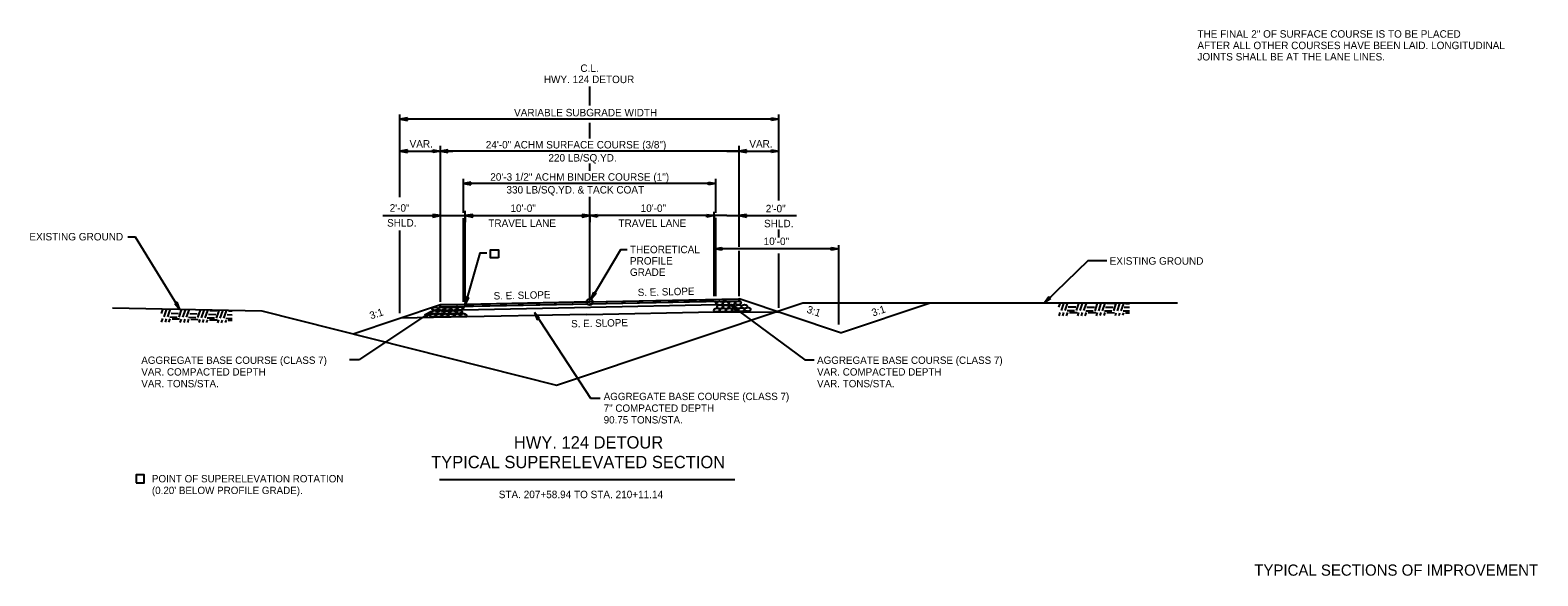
# Model space of a CAD drawing. Extents: x 1824008 to 1828864, y 689441 to 689870.
# Drawn here: x 1828742.7 to 1828863.8, y 689611.6 to 689655.5 of the extents above; entities that cross this region are included whole.
import ezdxf

# ---------------------------------------------------------------- set-up
doc = ezdxf.new("R2010")
doc.units = 0
for name, color, linetype in [('1', 7, 'Continuous'), ('19', 7, 'Continuous'), ('42', 7, 'Continuous'), ('Level 1', 7, 'Continuous'), ('Level 9', 7, 'Continuous'), ('R_Draft', 7, 'Continuous'), ('R_Horz Alg', 7, 'Continuous')]:
    doc.layers.add(name, color=color, linetype=linetype)

# ---------------------------------------------------------------- blocks, each defined once
blk = doc.blocks.new('ROCKS')
at = {"layer": '1'}
blk.add_spline([(0.013, 0.06), (0.053, 0.053), (0.107, 0.033), (0.133, 0.013), (0.133, -0.007), (0.12, -0.033), (0.107, -0.04), (0.073, -0.053), (0.033, -0.067), (0.013, -0.067), (-0.02, -0.06), (-0.06, -0.053), (-0.087, -0.047), (-0.113, -0.02), (-0.113, -0.007), (-0.107, 0.02), (-0.087, 0.033), (-0.067, 0.047), (-0.033, 0.053), (-0.02, 0.06), (0.013, 0.06)], degree=3, dxfattribs=at)

msp = doc.modelspace()

# ---------------------------------------------------------------- linework, layer by layer
at = {"layer": '1'}
for p, q in [((1828772.95, 689648.43), (1828772.35, 689648.33)), ((1828772.35, 689648.33), (1828772.95, 689648.22)), ((1828772.95, 689648.38), (1828772.51, 689648.34)), ((1828772.51, 689648.31), (1828772.95, 689648.27)), ((1828772.95, 689648.22), (1828772.95, 689648.43)), ((1828802.2, 689648.22), (1828802.2, 689648.43)), ((1828802.2, 689648.43), (1828802.8, 689648.33)), ((1828802.2, 689648.38), (1828802.64, 689648.34)), ((1828802.8, 689648.33), (1828802.2, 689648.22)), ((1828802.64, 689648.31), (1828802.2, 689648.27)), ((1828772.95, 689645.85), (1828772.35, 689645.74)), ((1828772.35, 689645.74), (1828772.95, 689645.64)), ((1828772.95, 689645.79), (1828772.51, 689645.76)), ((1828772.51, 689645.73), (1828772.95, 689645.69)), ((1828772.95, 689645.64), (1828772.95, 689645.85)), ((1828775, 689645.64), (1828775, 689645.85)), ((1828775, 689645.85), (1828775.6, 689645.74)), ((1828775, 689645.79), (1828775.44, 689645.76)), ((1828775.6, 689645.74), (1828775, 689645.64)), ((1828775.44, 689645.73), (1828775, 689645.69)), ((1828776.2, 689645.85), (1828775.6, 689645.74)), ((1828775.6, 689645.74), (1828776.2, 689645.64)), ((1828776.2, 689645.79), (1828775.76, 689645.76)), ((1828775.76, 689645.73), (1828776.2, 689645.69)), ((1828776.2, 689645.64), (1828776.2, 689645.85)), ((1828800.2, 689645.85), (1828799.6, 689645.74)), ((1828799.6, 689645.74), (1828800.2, 689645.64)), ((1828800.2, 689645.79), (1828799.76, 689645.76)), ((1828799.76, 689645.73), (1828800.2, 689645.69)), ((1828800.2, 689645.64), (1828800.2, 689645.85)), ((1828802.2, 689645.64), (1828802.2, 689645.85)), ((1828802.2, 689645.85), (1828802.8, 689645.74)), ((1828802.2, 689645.79), (1828802.64, 689645.76)), ((1828802.8, 689645.74), (1828802.2, 689645.64)), ((1828802.64, 689645.73), (1828802.2, 689645.69)), ((1828778.05, 689643.26), (1828777.45, 689643.15)), ((1828777.45, 689643.15), (1828778.05, 689643.05)), ((1828778.05, 689643.2), (1828777.61, 689643.17)), ((1828777.61, 689643.14), (1828778.05, 689643.1)), ((1828778.05, 689643.05), (1828778.05, 689643.26)), ((1828797.14, 689643.05), (1828797.14, 689643.26)), ((1828797.14, 689643.26), (1828797.74, 689643.15)), ((1828797.14, 689643.2), (1828797.58, 689643.17)), ((1828797.74, 689643.15), (1828797.14, 689643.05)), ((1828797.58, 689643.14), (1828797.14, 689643.1)), ((1828775, 689640.67), (1828775, 689640.46)), ((1828775.6, 689640.57), (1828775, 689640.67)), ((1828777.6, 689633.64), (1828777.6, 689640.97)), ((1828778.2, 689640.67), (1828777.6, 689640.57)), ((1828778.2, 689640.46), (1828778.2, 689640.67)), ((1828787, 689640.67), (1828787, 689640.46)), ((1828787.6, 689640.57), (1828787, 689640.67)), ((1828787, 689640.67), (1828787, 689640.46)), ((1828787.6, 689640.57), (1828787, 689640.67)), ((1828787.6, 689640.57), (1828788.2, 689640.67)), ((1828787.6, 689640.57), (1828788.2, 689640.67)), ((1828788.2, 689640.67), (1828788.2, 689640.46)), ((1828788.2, 689640.67), (1828788.2, 689640.46)), ((1828797, 689640.46), (1828797, 689640.67)), ((1828797, 689640.67), (1828797.6, 689640.57)), ((1828797.6, 689634.09), (1828797.6, 689640.87)), ((1828799.6, 689638.07), (1828799.6, 689640.87)), ((1828800.2, 689640.67), (1828799.6, 689640.57)), ((1828800.2, 689640.46), (1828800.2, 689640.67)), ((1828775.44, 689640.58), (1828775, 689640.62)), ((1828775, 689640.46), (1828775.6, 689640.57)), ((1828775, 689640.51), (1828775.44, 689640.55)), ((1828776.6, 689640.57), (1828787.6, 689640.57)), ((1828777.6, 689640.57), (1828787.6, 689640.57)), ((1828777.6, 689640.57), (1828778.2, 689640.46)), ((1828777.6, 689640.57), (1828777.6, 689640.05)), ((1828778.2, 689640.62), (1828777.76, 689640.58)), ((1828777.76, 689640.55), (1828778.2, 689640.51)), ((1828787.44, 689640.58), (1828787, 689640.62)), ((1828787.44, 689640.58), (1828787, 689640.62)), ((1828787, 689640.46), (1828787.6, 689640.57)), ((1828787, 689640.46), (1828787.6, 689640.57)), ((1828787, 689640.51), (1828787.44, 689640.55)), ((1828787, 689640.51), (1828787.44, 689640.55)), ((1828797.6, 689640.57), (1828787.6, 689640.57)), ((1828788.2, 689640.46), (1828787.6, 689640.57)), ((1828797.6, 689640.57), (1828787.6, 689640.57)), ((1828788.2, 689640.46), (1828787.6, 689640.57)), ((1828798.6, 689640.57), (1828787.6, 689640.57)), ((1828787.6, 689640.57), (1828787.6, 689640.05)), ((1828787.76, 689640.58), (1828788.2, 689640.62)), ((1828787.76, 689640.58), (1828788.2, 689640.62)), ((1828788.2, 689640.51), (1828787.76, 689640.55)), ((1828788.2, 689640.51), (1828787.76, 689640.55)), ((1828797, 689640.62), (1828797.44, 689640.58)), ((1828797.6, 689640.57), (1828797, 689640.46)), ((1828797.44, 689640.55), (1828797, 689640.51)), ((1828797.6, 689640.57), (1828797.6, 689640.05)), ((1828797.74, 689634.09), (1828797.74, 689640.4)), ((1828799.6, 689640.57), (1828800.2, 689640.46)), ((1828800.2, 689640.62), (1828799.76, 689640.58)), ((1828799.76, 689640.55), (1828800.2, 689640.51)), ((1828797.6, 689637.91), (1828798.2, 689638.01)), ((1828807.33, 689637.91), (1828797.6, 689637.91)), ((1828798.2, 689637.8), (1828797.6, 689637.91)), ((1828797.76, 689637.92), (1828798.2, 689637.96)), ((1828798.2, 689637.85), (1828797.76, 689637.89)), ((1828798.2, 689638.01), (1828798.2, 689637.8)), ((1828799.6, 689634.09), (1828799.6, 689637.75)), ((1828807, 689637.8), (1828807, 689638.01)), ((1828807, 689638.01), (1828807.6, 689637.91)), ((1828807, 689637.96), (1828807.44, 689637.92)), ((1828807.6, 689637.91), (1828807, 689637.8)), ((1828807.44, 689637.89), (1828807, 689637.85)), ((1828777.6, 689633.44), (1828775.6, 689633.4)), ((1828777.6, 689633.64), (1828777.6, 689633.44)), ((1828784.92, 689626.96), (1828804.73, 689633.56)), ((1828807.74, 689631.16), (1828799.6, 689633.88)), ((1828804.73, 689633.56), (1828834.81, 689633.56)), ((1828807.74, 689631.16), (1828814.94, 689633.56)), ((1828824.49, 689634.06), (1828824.13, 689633.57)), ((1828824.13, 689633.57), (1828824.63, 689633.91)), ((1828824.52, 689634.02), (1828824.23, 689633.69)), ((1828824.25, 689633.67), (1828824.59, 689633.94)), ((1828824.63, 689633.91), (1828824.49, 689634.06)), ((1828749.26, 689633.15), (1828761.26, 689632.91)), ((1828775.6, 689633.4), (1828768.59, 689631.06)), ((1828776.37, 689632.42), (1828772.42, 689632.34)), ((1828775.54, 689619.37), (1828799.26, 689619.37))]:
    msp.add_line(p, q, dxfattribs=at)
for points in [[(1828829.14, 689636.93), (1828827.6, 689636.93), (1828824.13, 689633.57)], [(1828761.26, 689632.91), (1828784.92, 689626.96)]]:
    msp.add_lwpolyline(points, dxfattribs=at)
msp.add_circle((1828787.6, 689633.64), 0.25, dxfattribs=at)
at = {"layer": '19'}
for p, q in [((1828772.35, 689642.05), (1828772.35, 689648.69)), ((1828802.8, 689648.33), (1828772.35, 689648.33)), ((1828802.8, 689641.8), (1828802.8, 689648.69)), ((1828775.6, 689640.79), (1828775.6, 689646.17)), ((1828799.6, 689645.74), (1828775.6, 689645.74)), ((1828799.6, 689640.79), (1828799.6, 689646.17)), ((1828777.45, 689640.79), (1828777.45, 689643.53)), ((1828797.74, 689643.15), (1828777.45, 689643.15)), ((1828797.74, 689640.79), (1828797.74, 689643.53)), ((1828802.8, 689638.81), (1828802.8, 689639.46)), ((1828772.35, 689632.74), (1828772.35, 689639.38)), ((1828802.8, 689633.15), (1828802.8, 689637.53)), ((1828787.64, 689633.47), (1828777.52, 689633.27)), ((1828777.6, 689633.44), (1828777.66, 689634.04)), ((1828777.86, 689633.99), (1828777.6, 689633.44)), ((1828787.6, 689633.64), (1828777.6, 689633.44)), ((1828777.63, 689633.59), (1828777.71, 689634.02)), ((1828777.66, 689634.04), (1828777.86, 689633.99)), ((1828777.82, 689633.99), (1828777.66, 689633.59)), ((1828787.6, 689633.64), (1828797.6, 689633.84)), ((1828797.68, 689633.67), (1828787.64, 689633.47)), ((1828787.65, 689633.22), (1828797.81, 689633.42)), ((1828797.6, 689633.84), (1828799.6, 689633.88)), ((1828797.81, 689633.42), (1828797.68, 689633.67)), ((1828774.88, 689632.86), (1828769.06, 689628.98)), ((1828774.88, 689632.86), (1828774.33, 689632.58)), ((1828774.33, 689632.58), (1828774.46, 689632.41)), ((1828774.74, 689632.77), (1828774.36, 689632.54)), ((1828774.43, 689632.46), (1828774.76, 689632.75)), ((1828774.46, 689632.41), (1828774.88, 689632.86)), ((1828787.37, 689632.64), (1828776.37, 689632.42)), ((1828777.52, 689633.27), (1828777.39, 689633.01)), ((1828777.39, 689633.01), (1828787.65, 689633.22)), ((1828783.16, 689632.79), (1828787.66, 689625.91)), ((1828783.55, 689632.32), (1828783.16, 689632.79)), ((1828783.16, 689632.79), (1828783.37, 689632.21)), ((1828783.23, 689632.64), (1828783.41, 689632.24)), ((1828783.5, 689632.29), (1828783.25, 689632.65)), ((1828783.37, 689632.21), (1828783.55, 689632.32)), ((1828787.37, 689632.64), (1828797.63, 689632.84)), ((1828797.63, 689632.84), (1828802.8, 689632.81)), ((1828799.47, 689633.11), (1828798.92, 689633.38)), ((1828798.92, 689633.38), (1828799.34, 689632.94)), ((1828798.92, 689633.38), (1828804.87, 689628.98)), ((1828799.04, 689633.27), (1828799.37, 689632.98)), ((1828799.44, 689633.06), (1828799.06, 689633.3)), ((1828799.34, 689632.94), (1828799.47, 689633.11)), ((1828769.06, 689628.98), (1828768.29, 689628.98)), ((1828804.87, 689628.98), (1828805.63, 689628.98)), ((1828787.66, 689625.91), (1828788.43, 689625.91))]:
    msp.add_line(p, q, dxfattribs=at)
msp.add_lwpolyline([(1828775.55, 689633.23), (1828775.55, 689633.23), (1828775.64, 689633.4), (1828799.55, 689633.88), (1828799.64, 689633.71)], close=True, dxfattribs=at)
at = {"layer": '42'}
for p, q in [((1828825.28, 689633.21), (1828825.38, 689633.51)), ((1828825.49, 689632.94), (1828825.68, 689633.51)), ((1828825.79, 689632.94), (1828825.98, 689633.5)), ((1828826.69, 689632.94), (1828826.89, 689633.51)), ((1828826.99, 689632.94), (1828827.19, 689633.51)), ((1828827.29, 689632.94), (1828827.49, 689633.52)), ((1828828.19, 689632.93), (1828828.39, 689633.53)), ((1828828.24, 689633.53), (1828828.24, 689633.53)), ((1828828.49, 689632.93), (1828828.69, 689633.53)), ((1828828.79, 689632.93), (1828828.99, 689633.53)), ((1828829.14, 689633.53), (1828829.74, 689633.52)), ((1828829.69, 689632.92), (1828829.89, 689633.52)), ((1828829.99, 689632.92), (1828830.19, 689633.52)), ((1828830.29, 689632.92), (1828830.49, 689633.52)), ((1828830.64, 689633.52), (1828830.96, 689633.52)), ((1828753.21, 689632.71), (1828753.31, 689633.02)), ((1828753.21, 689632.02), (1828753.31, 689632.3)), ((1828753.41, 689632.45), (1828753.61, 689633.01)), ((1828753.51, 689632.01), (1828753.61, 689632.29)), ((1828753.71, 689632.44), (1828753.91, 689633)), ((1828753.8, 689632), (1828753.91, 689632.29)), ((1828753.86, 689632.44), (1828754.46, 689632.42)), ((1828753.97, 689632.73), (1828754.57, 689632.72)), ((1828754.06, 689632.28), (1828754.66, 689632.27)), ((1828754.61, 689632.42), (1828754.82, 689632.99)), ((1828754.71, 689631.99), (1828754.81, 689632.26)), ((1828754.91, 689632.41), (1828755.12, 689632.98)), ((1828755.01, 689631.98), (1828755.11, 689632.26)), ((1828755.21, 689632.4), (1828755.42, 689632.98)), ((1828755.31, 689631.98), (1828755.41, 689632.25)), ((1828755.36, 689632.4), (1828755.96, 689632.38)), ((1828755.47, 689632.7), (1828756.07, 689632.68)), ((1828755.56, 689632.24), (1828756.11, 689632.23)), ((1828756.11, 689632.38), (1828756.33, 689632.98)), ((1828756.11, 689632.23), (1828756.16, 689632.23)), ((1828756.17, 689632.98), (1828756.18, 689632.98)), ((1828756.22, 689631.98), (1828756.31, 689632.23)), ((1828756.41, 689632.37), (1828756.63, 689632.97)), ((1828756.52, 689631.98), (1828756.61, 689632.22)), ((1828756.71, 689632.37), (1828756.93, 689632.96)), ((1828756.82, 689631.98), (1828756.91, 689632.21)), ((1828756.86, 689632.36), (1828757.46, 689632.35)), ((1828756.97, 689632.66), (1828757.57, 689632.64)), ((1828757.06, 689632.21), (1828757.66, 689632.19)), ((1828757.08, 689632.96), (1828757.68, 689632.94)), ((1828757.61, 689632.34), (1828757.83, 689632.94)), ((1828757.91, 689632.34), (1828758.13, 689632.93)), ((1828758.21, 689632.33), (1828758.43, 689632.92)), ((1828758.36, 689632.32), (1828758.87, 689632.31)), ((1828758.47, 689632.62), (1828758.88, 689632.61)), ((1828758.58, 689632.92), (1828758.89, 689632.91)), ((1828825.3, 689632.51), (1828825.39, 689632.8)), ((1828825.59, 689632.51), (1828825.69, 689632.79)), ((1828825.89, 689632.51), (1828825.99, 689632.79)), ((1828825.94, 689632.94), (1828826.54, 689632.94)), ((1828826.04, 689633.24), (1828826.64, 689633.24)), ((1828826.14, 689632.79), (1828826.74, 689632.79)), ((1828826.8, 689632.51), (1828826.89, 689632.79)), ((1828827.1, 689632.51), (1828827.19, 689632.79)), ((1828827.4, 689632.52), (1828827.49, 689632.78)), ((1828827.44, 689632.93), (1828828.04, 689632.93)), ((1828827.54, 689633.23), (1828828.14, 689633.23)), ((1828827.64, 689632.78), (1828828.19, 689632.78)), ((1828828.19, 689632.78), (1828828.24, 689632.78)), ((1828828.31, 689632.53), (1828828.39, 689632.78)), ((1828828.61, 689632.54), (1828828.69, 689632.78)), ((1828828.91, 689632.54), (1828828.99, 689632.78)), ((1828828.94, 689632.93), (1828829.54, 689632.92)), ((1828829.04, 689633.23), (1828829.64, 689633.22)), ((1828829.14, 689632.78), (1828829.74, 689632.77)), ((1828829.82, 689632.56), (1828829.89, 689632.77)), ((1828830.12, 689632.56), (1828830.19, 689632.77)), ((1828830.43, 689632.58), (1828830.49, 689632.77)), ((1828830.44, 689632.92), (1828830.95, 689632.92)), ((1828830.54, 689633.22), (1828830.95, 689633.22)), ((1828830.64, 689632.77), (1828830.95, 689632.77)), ((1828757.73, 689631.97), (1828757.81, 689632.19)), ((1828758.03, 689631.97), (1828758.11, 689632.18)), ((1828758.34, 689631.98), (1828758.41, 689632.17)), ((1828758.56, 689632.17), (1828758.87, 689632.16))]:
    msp.add_line(p, q, dxfattribs=at)
at = {"layer": 'Level 9'}
msp.add_lwpolyline([(1828779.33, 689637.56), (1828778.76, 689637.56), (1828777.6, 689633.44)], dxfattribs=at)
at = {"layer": 'R_Draft'}
for p, q in [((1828787.6, 689649.42), (1828787.6, 689650.96)), ((1828787.6, 689646.78), (1828787.6, 689648.02)), ((1828772.35, 689645.74), (1828776.6, 689645.74)), ((1828798.6, 689645.74), (1828802.8, 689645.74)), ((1828787.6, 689644.17), (1828787.6, 689644.76)), ((1828799.6, 689644.06), (1828799.6, 689644.6)), ((1828787.6, 689633.64), (1828787.6, 689642.08)), ((1828775.6, 689633.64), (1828775.6, 689640.87)), ((1828787, 689640.67), (1828787, 689640.46)), ((1828787.6, 689640.57), (1828787, 689640.67)), ((1828787.6, 689640.57), (1828788.2, 689640.67)), ((1828788.2, 689640.67), (1828788.2, 689640.46)), ((1828770.99, 689640.57), (1828776.6, 689640.57)), ((1828777.6, 689640.57), (1828787.6, 689640.57)), ((1828787.44, 689640.58), (1828787, 689640.62)), ((1828787, 689640.46), (1828787.6, 689640.57)), ((1828787, 689640.51), (1828787.44, 689640.55)), ((1828797.6, 689640.57), (1828787.6, 689640.57)), ((1828788.2, 689640.46), (1828787.6, 689640.57)), ((1828787.76, 689640.58), (1828788.2, 689640.62)), ((1828788.2, 689640.51), (1828787.76, 689640.55)), ((1828798.6, 689640.57), (1828804.22, 689640.57)), ((1828754.46, 689633.61), (1828754.28, 689633.5)), ((1828754.28, 689633.5), (1828754.68, 689633.04)), ((1828754.32, 689633.52), (1828754.59, 689633.17)), ((1828754.61, 689633.18), (1828754.41, 689633.57)), ((1828754.68, 689633.04), (1828754.46, 689633.61)), ((1828787.72, 689633.85), (1828787.94, 689634.42)), ((1828788.12, 689634.32), (1828787.72, 689633.85)), ((1828787.8, 689634), (1828787.98, 689634.39)), ((1828788.08, 689634.34), (1828787.82, 689633.98)), ((1828787.94, 689634.42), (1828788.12, 689634.32))]:
    msp.add_line(p, q, dxfattribs=at)
for points in [[(1828750.49, 689638.88), (1828751.09, 689638.88), (1828754.68, 689633.04)], [(1828790.6, 689637.83), (1828790.07, 689637.83), (1828787.72, 689633.85)]]:
    msp.add_lwpolyline(points, dxfattribs=at)
for points in [[(1828780.26, 689637.18), (1828779.62, 689637.18), (1828779.62, 689637.82), (1828780.26, 689637.82)], [(1828751.17, 689619.11), (1828751.81, 689619.11), (1828751.81, 689619.75), (1828751.17, 689619.75)]]:
    msp.add_lwpolyline(points, close=True, dxfattribs=at)
at = {"layer": 'R_Horz Alg'}
for p, q in [((1828777.45, 689633.64), (1828777.45, 689640.36)), ((1828807.6, 689631.83), (1828807.6, 689638.21))]:
    msp.add_line(p, q, dxfattribs=at)

# ---------------------------------------------------------------- block references
at = {"layer": 'Level 1'}
for p, xscale, yscale, rotation in [((1828798.02, 689633.54), 2.0116542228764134, 2.0116542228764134, 2.1985669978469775), ((1828798.51, 689633.53), 2.0116542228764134, 2.0116542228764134, 2.1985669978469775), ((1828799.01, 689633.55), 2.0116542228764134, 2.0116542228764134, 2.1985669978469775), ((1828799.51, 689633.56), 2.0116542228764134, 2.0116542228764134, 2.1985669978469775), ((1828800.01, 689633.27), 2.0116542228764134, 2.0116542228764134, 2.1985669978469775), ((1828775.01, 689632.57), 2.011654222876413, -2.011654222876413, 178.81230068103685), ((1828775.15, 689632.82), 2.011654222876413, -2.011654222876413, 178.81230068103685), ((1828775.19, 689633.09), 2.011654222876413, -2.011654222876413, 178.81230068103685), ((1828775.49, 689632.57), 2.011654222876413, -2.011654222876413, 178.81230068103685), ((1828775.64, 689632.82), 2.011654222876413, -2.011654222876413, 178.81230068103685), ((1828775.7, 689633.09), 2.011654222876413, -2.011654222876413, 178.81230068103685), ((1828775.98, 689632.57), 2.011654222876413, -2.011654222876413, 178.81230068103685), ((1828776.14, 689632.81), 2.011654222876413, -2.011654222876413, 178.81230068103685), ((1828776.2, 689633.08), 2.011654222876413, -2.011654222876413, 178.81230068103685), ((1828776.48, 689632.56), 2.011654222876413, -2.011654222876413, 178.81230068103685), ((1828776.64, 689632.82), 2.011654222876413, -2.011654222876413, 178.81230068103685), ((1828776.7, 689633.09), 2.011654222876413, -2.011654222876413, 178.81230068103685), ((1828776.98, 689632.57), 2.011654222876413, -2.011654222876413, 178.81230068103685), ((1828777.13, 689632.84), 2.011654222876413, -2.011654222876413, 178.81230068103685), ((1828777.2, 689633.11), 2.011654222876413, -2.011654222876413, 178.81230068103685), ((1828777.47, 689632.58), 2.011654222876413, -2.011654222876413, 178.81230068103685), ((1828797.78, 689632.99), 2.0116542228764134, 2.0116542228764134, 2.1985669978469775), ((1828798.03, 689633.25), 2.0116542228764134, 2.0116542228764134, 2.1985669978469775), ((1828798.28, 689632.99), 2.0116542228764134, 2.0116542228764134, 2.1985669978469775), ((1828798.52, 689633.24), 2.0116542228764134, 2.0116542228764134, 2.1985669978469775), ((1828798.78, 689632.99), 2.0116542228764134, 2.0116542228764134, 2.1985669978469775), ((1828799.02, 689633.24), 2.0116542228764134, 2.0116542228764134, 2.1985669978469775), ((1828799.28, 689633.01), 2.0116542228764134, 2.0116542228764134, 2.1985669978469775), ((1828799.52, 689633.26), 2.0116542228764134, 2.0116542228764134, 2.1985669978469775), ((1828799.77, 689633.02), 2.0116542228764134, 2.0116542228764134, 2.1985669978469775), ((1828800.27, 689633.04), 2.0116542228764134, 2.0116542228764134, 2.1985669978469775)]:
    msp.add_blockref('ROCKS', p, dxfattribs=dict(at, xscale=xscale, yscale=yscale, rotation=rotation))

# ---------------------------------------------------------------- texts
at = {"layer": '1'}
for s, height, rotation, p in [('HWY. 124 DETOUR', 0.6, 360, (1828783.91, 689651.22)), ('C.L.', 0.6, 360, (1828786.85, 689652.12)), ('3:1', 0.6, 18.4349, (1828770.03, 689632.23)), ('3:1', 0.6, 341.5179, (1828804.98, 689632.79)), ('3:1', 0.6, 18.4349, (1828810.36, 689632.46)), ('HWY. 124 DETOUR', 0.99, 359.9954, (1828781.51, 689621.86)), ('TYPICAL SUPERELEVATED SECTION ', 0.99, 359.9954, (1828774.86, 689620.28))]:
    msp.add_text(s, height=height, rotation=rotation, dxfattribs=at).set_placement(p)
for s, height, p in [('VARIABLE SUBGRADE WIDTH', 0.6, (1828781.52, 689648.55)), ('24\'-0" ACHM SURFACE COURSE (3/8")', 0.6, (1828779.25, 689645.97)), ('220 LB/SQ.YD.', 0.6, (1828784.28, 689644.92)), ('20\'-3 1/2" ACHM BINDER COURSE (1")', 0.6, (1828779.61, 689643.38)), ('330 LB/SQ.YD. & TACK COAT', 0.6, (1828780.91, 689642.35)), ('SHLD.', 0.6, (1828801.6, 689639.64)), ('TYPICAL SECTIONS OF IMPROVEMENT', 0.9, (1828840.98, 689611.64))]:
    msp.add_text(s, height=height, dxfattribs=at).set_placement(p)
at = {"layer": '19'}
for s, p in [('THE FINAL 2" OF SURFACE COURSE IS TO BE PLACED', (1828836.41, 689654.87)), ('AFTER ALL OTHER COURSES HAVE BEEN LAID. LONGITUDINAL', (1828836.41, 689653.95)), ('JOINTS SHALL BE AT THE LANE LINES.', (1828836.41, 689653.04))]:
    msp.add_text(s, height=0.6, dxfattribs=at).set_placement(p)
for s, p in [('AGGREGATE BASE COURSE (CLASS 7)', (1828751.58, 689628.66)), ('AGGREGATE BASE COURSE (CLASS 7)', (1828805.86, 689628.66)), ('VAR. COMPACTED DEPTH', (1828751.58, 689627.72)), ('VAR. TONS/STA.', (1828751.58, 689626.78)), ('VAR. COMPACTED DEPTH', (1828805.86, 689627.72)), ('VAR. TONS/STA.', (1828805.86, 689626.78)), ('AGGREGATE BASE COURSE (CLASS 7)', (1828788.72, 689625.75)), ('7" COMPACTED DEPTH', (1828788.72, 689624.81)), ('90.75 TONS/STA.', (1828788.72, 689623.87))]:
    msp.add_text(s, height=0.59, rotation=360, dxfattribs=at).set_placement(p)
at = {"layer": 'R_Draft'}
for s, height, p in [('VAR.', 0.6, (1828773.13, 689646.04)), ('VAR.', 0.6, (1828800.42, 689646.04)), ('10\'-0"', 0.6, (1828791.69, 689640.87)), ('2\'-0"', 0.6, (1828801.74, 689640.84)), ('TRAVEL LANE', 0.6, (1828789.91, 689639.67)), ('EXISTING GROUND', 0.6, (1828742.59, 689638.58)), ('10\'-0"', 0.6, (1828801.57, 689638.21)), ('EXISTING GROUND', 0.6, (1828829.36, 689636.63)), ('POINT OF SUPERELEVATION ROTATION', 0.59, (1828752.43, 689619.14)), ("(0.20' BELOW PROFILE GRADE).", 0.59, (1828752.43, 689618.2))]:
    msp.add_text(s, height=height, dxfattribs=at).set_placement(p)
for s, height, rotation, p in [('2\'-0"', 0.6, 360, (1828771.53, 689640.89)), ('10\'-0"', 0.6, 360, (1828781.23, 689640.87)), ('SHLD.', 0.6, 360, (1828771.32, 689639.69)), ('TRAVEL LANE', 0.6, 360, (1828779.45, 689639.67)), ('THEORETICAL', 0.6, 360, (1828790.83, 689637.55)), ('PROFILE', 0.6, 360, (1828790.83, 689636.64)), ('GRADE', 0.6, 360, (1828790.83, 689635.73)), ('S. E. SLOPE', 0.59, 1.2584, (1828791.46, 689634.11)), ('S. E. SLOPE', 0.59, 1.2584, (1828779.89, 689633.83)), ('S. E. SLOPE', 0.59, 1.2584, (1828786.11, 689631.59)), ('STA. 207+58.94 TO STA. 210+11.14', 0.6, 359.9954, (1828780.29, 689617.87))]:
    msp.add_text(s, height=height, rotation=rotation, dxfattribs=at).set_placement(p)

doc.saveas('drawing.dxf')
